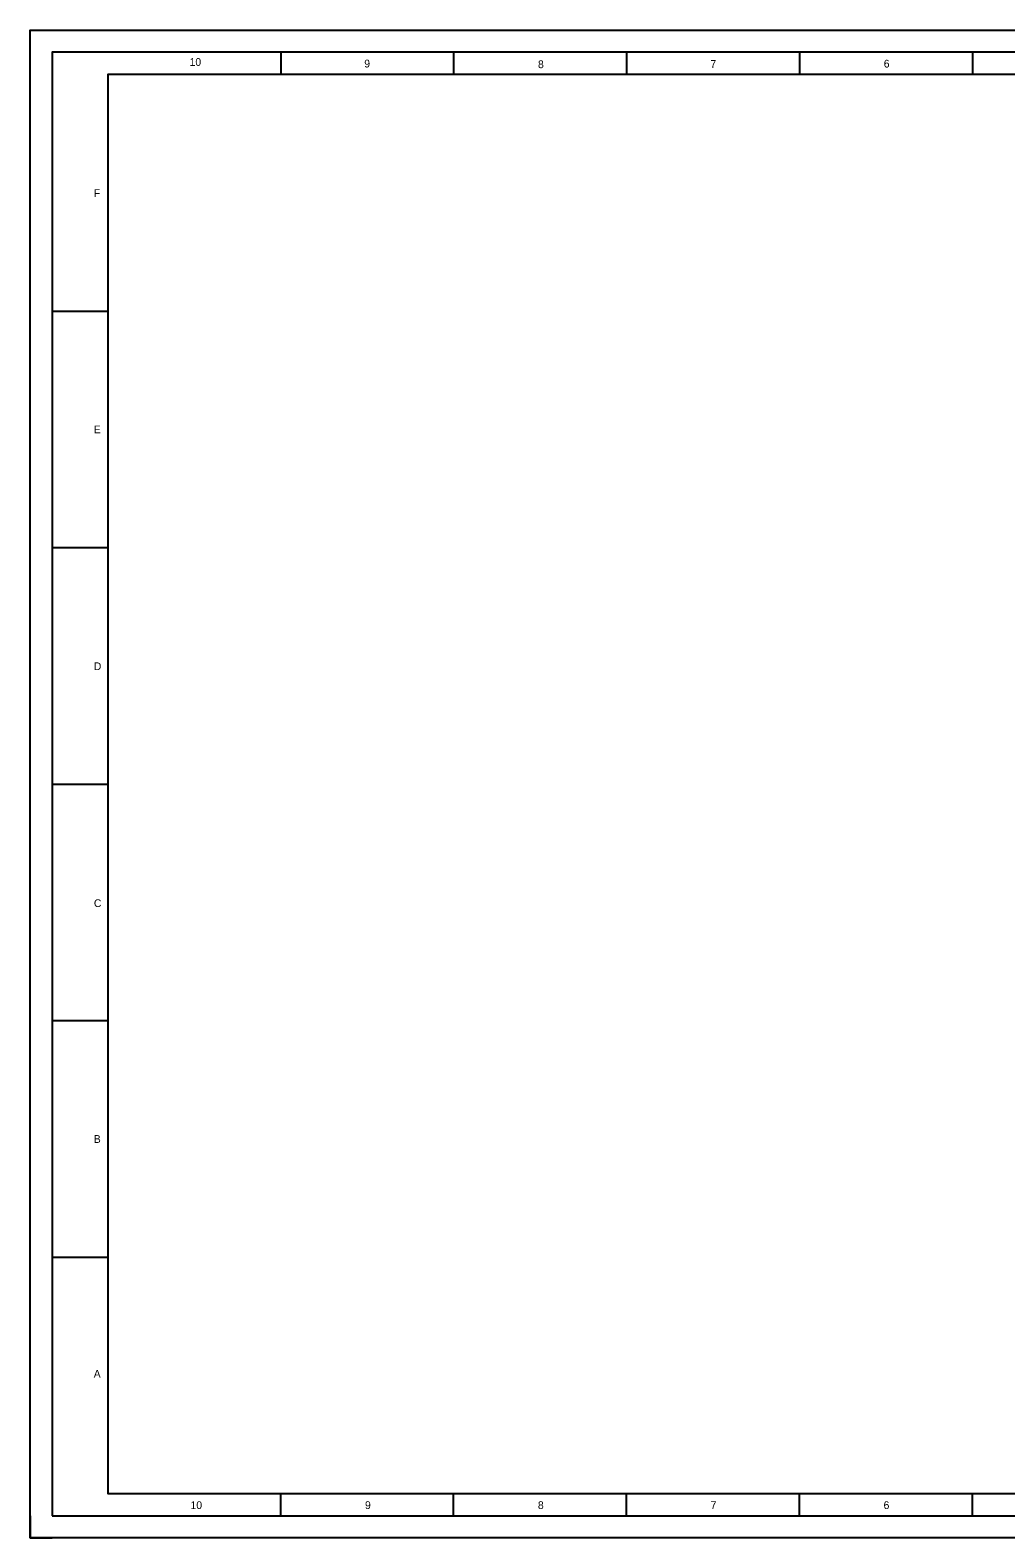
# Model space of a CAD drawing. Extents: x 1945213.1 to 1945257.1, y 2038820.4 to 2038854.4.
# Drawn here: x 1945213.14 to 1945235.14, y 2038820.38 to 2038854.38 of the extents above; entities that cross this region are included whole.
import ezdxf

# ---------------------------------------------------------------- set-up
doc = ezdxf.new("R2010")
doc.units = 0
doc.layers.add('G-ANNO-NPLT', color=7, linetype='Continuous')
doc.layers.add('G-ANNO-TTLB', color=7, linetype='Continuous')

msp = doc.modelspace()

# ---------------------------------------------------------------- linework, layer by layer
at = {"layer": 'G-ANNO-NPLT'}
msp.add_lwpolyline([(1945213.137, 2038854.377), (1945257.137, 2038854.377), (1945257.137, 2038820.377), (1945213.137, 2038820.377)], close=True, dxfattribs=at)
for points in [[(1945213.137, 2038853.877), (1945213.137, 2038854.377), (1945213.637, 2038854.377)], [(1945213.137, 2038820.877), (1945213.137, 2038820.377), (1945213.637, 2038820.377)]]:
    msp.add_lwpolyline(points, dxfattribs=at)
at = {"layer": 'G-ANNO-TTLB'}
for p, q in [((1945218.787, 2038853.877), (1945218.787, 2038853.377)), ((1945222.687, 2038853.877), (1945222.687, 2038853.377)), ((1945222.687, 2038853.877), (1945222.687, 2038853.377)), ((1945226.587, 2038853.877), (1945226.587, 2038853.377)), ((1945230.487, 2038853.877), (1945230.487, 2038853.377)), ((1945234.387, 2038853.877), (1945234.387, 2038853.377)), ((1945213.637, 2038848.042), (1945214.887, 2038848.042)), ((1945213.637, 2038842.709), (1945214.887, 2038842.709)), ((1945213.637, 2038837.376), (1945214.887, 2038837.376)), ((1945213.637, 2038832.043), (1945214.887, 2038832.043)), ((1945213.637, 2038826.71), (1945214.887, 2038826.71)), ((1945218.787, 2038820.877), (1945218.787, 2038821.377)), ((1945222.687, 2038820.877), (1945222.687, 2038821.377)), ((1945226.587, 2038820.877), (1945226.587, 2038821.377)), ((1945230.487, 2038820.877), (1945230.487, 2038821.377)), ((1945234.387, 2038820.877), (1945234.387, 2038821.377))]:
    msp.add_line(p, q, dxfattribs=at)
for points in [[(1945213.637, 2038820.877), (1945256.637, 2038820.877), (1945256.637, 2038853.877), (1945213.637, 2038853.877)], [(1945256.137, 2038853.377), (1945214.887, 2038853.377), (1945214.887, 2038821.377), (1945256.137, 2038821.377)]]:
    msp.add_lwpolyline(points, close=True, dxfattribs=at)

# ---------------------------------------------------------------- texts
for s, p in [('10', (1945216.733, 2038853.572)), ('9', (1945220.671, 2038853.536)), ('8', (1945224.589, 2038853.52)), ('7', (1945228.476, 2038853.527)), ('6', (1945232.385, 2038853.534)), ('F', (1945214.573, 2038850.613)), ('E', (1945214.572, 2038845.286)), ('D', (1945214.573, 2038839.945)), ('C', (1945214.575, 2038834.602)), ('B', (1945214.573, 2038829.284)), ('A', (1945214.571, 2038823.989)), ('10', (1945216.754, 2038821.027)), ('9', (1945220.688, 2038821.027)), ('8', (1945224.587, 2038821.027)), ('7', (1945228.481, 2038821.027)), ('6', (1945232.381, 2038821.027))]:
    msp.add_text(s, height=0.175, rotation=360, dxfattribs=at).set_placement(p)

doc.saveas('drawing.dxf')
